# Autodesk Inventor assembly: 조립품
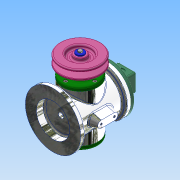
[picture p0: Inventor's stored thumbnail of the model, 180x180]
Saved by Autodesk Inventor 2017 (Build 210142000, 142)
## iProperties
Part Number: 조립품
Material: 일반
Document SubType Name: Assembly
Designer: Administrator
Author: Administrator
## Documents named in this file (18)
- C:\Users\Administrator\Desktop\730206V1005\조립품.iam
- C:\Users\Administrator\Desktop\730206V1005\본체.ipt
- C:\Users\Administrator\Desktop\730206V1005\베어링 17 x 40 x 12.ipt
- C:\Users\Administrator\Desktop\730206V1005\뒤커버.ipt
- C:\Users\Administrator\Desktop\730206V1005\앞커버.ipt
- C:\Users\Administrator\Desktop\730206V1005\오일 실 17 30 8.ipt
- C:\Users\Administrator\Desktop\730206V1005\볼트 M4 x 8.ipt
- C:\Users\Administrator\Desktop\730206V1005\편심축.ipt
- C:\Users\Administrator\Desktop\730206V1005\링크.ipt
- C:\Users\Administrator\Desktop\730206V1005\슬라이더.ipt
- C:\Users\Administrator\Desktop\730206V1005\클레비스 핀 6 x 22.ipt
- 클레비스 핀 6 x 22.ipt
- C:\Users\Administrator\Desktop\730206V1005\덮개.ipt
- C:\Users\Administrator\Desktop\730206V1005\키 4 x 4 x 12.ipt
- C:\Users\Administrator\Desktop\730206V1005\볼트 M4 x 10.ipt
- C:\Users\Administrator\Desktop\730206V1005\와셔 4x16.ipt
- C:\Users\Administrator\Desktop\730206V1005\V-벨트풀리.ipt
- C:\Users\Administrator\Desktop\730206V1005\E-링.ipt
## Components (2 placed, 2 different names)
1. V-벨트풀리:1
2. E-링:1
